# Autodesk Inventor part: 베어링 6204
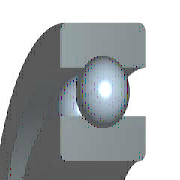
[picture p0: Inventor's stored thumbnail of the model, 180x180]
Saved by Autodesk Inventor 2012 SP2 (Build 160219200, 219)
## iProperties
IsCustomPart: 0
Created: 2009-02
Part Number: 베어링 6204
Material: 강, 연강
Description: 깊은 그루브 볼 베어링
Document SubType Name: Modeling
Standard: KS B 2023
Designer: KYOUNG IL JANG
Standards Organization: KS
Language: ko-KR
Size Designation: 6204 - 20 x 47 x 14
Categories: <MemberInstance><Categories><Category DisplayName="샤프트 부품" InternalName="7f7aeb1f-a693-4053-b835-cee3144e0d98" Mnemonic="SHFT"><Category DisplayName="베어링" Inter
Density: 7.86 g/cm^3
Mass: 104.255 g
Surface Area: 87.8912 cm^2
Volume: 13.264 cm^3
Author: KYOUNG IL JANG
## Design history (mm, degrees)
revolve "본체" stored, may be unused: angle "d6" = 90 deg
revolve "볼" stored, may be unused: angle "d7" = 90 deg
pattern_circular "IDS_ARRAYBALL[SIMPL:T]" dims angle "d3" = 360 deg
body "Solid1"
sketch "스케치" dims "d0" = 7.02 (= -0.26 x WD + 0.26 x BD)
  geometry: L1 (3.49, 16.75)-(10.51, 16.75); L2 (7, 16.75)-(7, 13.24); L3 (7, 16.75)-(7, 20.26); L4 (4.392, 14.401)-(0, 14.401); L5 (0, 10)-(14, 10); L6 (4.392, 19.099)-(0, 19.099); L7 (0, 23.5)-(14, 23.5); L8 (14, 10)-(14, 14.401); L9 (9.608, 14.401)-(14, 14.401); L10 (9.608, 19.099)-(14, 19.099); L11 (14, 23.5)-(14, 19.099); L12 (-1.4, 0)-(8.4, 0) reference; L13 (0, -0.3)-(0, 5.3) reference
  constraints: 22 end point, 4 point on line, 2 collinear, 2 perpendicular, 2 symmetric about line, 1 midpoint, 1 parallel, 14 other
  dimensions: "d9" = 20 diameter of L5 L12 (= WD); "d11" = 47 diameter of L7 L12 (= BD); "d12" = 14 distance between parallel lines of L8 L13 (= KB); "d13" = 28.802 diameter of L9 L12 (= 0.326 x BD + 0.674 x WD)
fillet "모깎기1" dims "d1" = 1 (= KRS)
other parameters: "WD" = 20 [user parameter; used in 5 equation terms], "BD" = 47 [user parameter; used in 5 equation terms], "KB" = 14 [user parameter; used in 1 equation term], "KRS" = 1 [user parameter; used in 1 equation term], "d4" = 0, "d5" = 0, "d8" = 0, "d14" = 0, "d15" = 0, "BBA" = 0 [user parameter], "BC0" = 6550000 [user parameter], "BC" = 1.27e+07 [user parameter], "BR" = 23.5 (= 0.5 x BD) [user parameter]
